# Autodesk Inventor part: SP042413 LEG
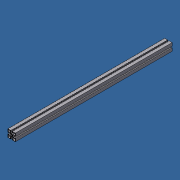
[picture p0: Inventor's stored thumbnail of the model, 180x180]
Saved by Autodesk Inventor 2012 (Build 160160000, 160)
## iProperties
Created: 2013-04
Part Number: SP042413 LEG
Material: Aluminum-6061
Description: PROFILE 45X45 UL
Document SubType Name: Modeling
Designer: Admin
Stock Number: 20.1063 PROFILE 45X45 UL
Density: 2.71 g/cm^3
FINISH: CLEAR ANODIZED
Author: Admin
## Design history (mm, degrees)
sketch "Sketch1"
  geometry: L1 (-4.1, -22.5)-(-4.1, -18) reference; L2 (-4.6, -18)-(-6.8, -18) reference; L3 (-6.8, -18)-(-6.8, -9.5) reference; L4 (-6.8, -9.5)-(-4.5, -7.2) reference; L5 (-4.5, -7.2)-(4.5, -7.2) reference; L6 (4.5, -7.2)-(6.8, -9.5) reference; L7 (6.8, -9.5)-(6.8, -18) reference; L8 (4.1, -18)-(4.1, -22.5) reference; L9 (22.5, -22.5)-(4.4, -22.5) reference; L10 (22.5, -4.4)-(22.5, -22.5) reference; L11 (22.5, -4.1)-(18, -4.1) reference; L12 (18, -4.6)-(18, -6.8) reference; L13 (18, -6.8)-(9.5, -6.8) reference; L14 (9.5, -6.8)-(7.2, -4.5) reference; L15 (7.2, -4.5)-(7.2, 4.5) reference; L16 (7.2, 4.5)-(9.5, 6.8) reference; L17 (9.5, 6.8)-(18, 6.8) reference; L18 (18, 4.1)-(22.5, 4.1) reference; L19 (4.4, 22.5)-(22.5, 22.5) reference; L20 (4.1, 22.5)-(4.1, 18) reference; L21 (4.6, 18)-(6.8, 18) reference; L22 (6.8, 18)-(6.8, 9.5) reference; L23 (6.8, 9.5)-(4.5, 7.2) reference; L24 (4.5, 7.2)-(-4.5, 7.2) reference; L25 (-4.5, 7.2)-(-6.8, 9.5) reference; L26 (-6.8, 9.5)-(-6.8, 18) reference; L27 (-4.1, 18)-(-4.1, 22.5) reference; L28 (-22.5, 4.1)-(-18, 4.1) reference; L29 (-18, 4.6)-(-18, 6.8) reference; L30 (-18, 6.8)-(-9.5, 6.8) reference; L31 (-9.5, 6.8)-(-7.2, 4.5) reference; L32 (-7.2, 4.5)-(-7.2, -4.5) reference; L33 (-7.2, -4.5)-(-9.5, -6.8) reference; L34 (-9.5, -6.8)-(-18, -6.8) reference; L35 (-18, -4.1)-(-22.5, -4.1) reference; L36 (-22.5, -22.5)-(-22.5, -4.4) reference; L37 (-21.1, -6.5)-(-19.4, -6.5) reference; L38 (-19.4, -6.5)-(-19.4, -8.2) reference; L39 (-8.2, -19.4)-(-6.5, -19.4) reference; L40 (-6.5, -19.4)-(-6.5, -21.1) reference; L41 (6.5, -21.1)-(6.5, -19.4) reference; L42 (6.5, -19.4)-(8.2, -19.4) reference; L43 (19.4, -8.2)-(19.4, -6.5) reference; L44 (19.4, -6.5)-(21.1, -6.5) reference; L45 (21.1, 6.5)-(19.4, 6.5) reference; L46 (19.4, 6.5)-(19.4, 8.2) reference; L47 (8.2, 19.4)-(6.5, 19.4) reference; L48 (6.5, 19.4)-(6.5, 21.1) reference; L49 (-6.5, 21.1)-(-6.5, 19.4) reference; L50 (-6.5, 19.4)-(-8.2, 19.4) reference; L51 (-19.4, 8.2)-(-19.4, 6.5) reference; L52 (-19.4, 6.5)-(-21.1, 6.5) reference; L53 (-3.537, -5.8)-(-1.188, -3.451) reference; L54 (-3.451, -1.188)-(-5.8, -3.537) reference; L55 (-5.8, -3.537)-(-5.8, 3.537) reference; L56 (-5.8, 3.537)-(-3.451, 1.188) reference; L57 (-1.188, 3.451)-(-3.537, 5.8) reference; L58 (-3.537, 5.8)-(3.537, 5.8) reference; L59 (3.537, 5.8)-(1.188, 3.451) reference; L60 (3.451, 1.188)-(5.8, 3.537) reference; L61 (5.8, 3.537)-(5.8, -3.537) reference; L62 (5.8, -3.537)-(3.451, -1.188) reference; L63 (1.188, -3.451)-(3.537, -5.8) reference; L64 (3.537, -5.8)-(-3.537, -5.8) reference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; A1 r 3.65 centre (0, 0) between (3.287, 1.588) and (1.588, 3.287) reference; A2 r 3.65 centre (0, 0) between (1.588, 3.287) and (1.188, 3.451) reference; A3 r 3.65 centre (0, 0) between (-1.188, 3.451) and (-3.451, 1.188) reference; A4 r 3.65 centre (0, 0) between (-3.451, -1.188) and (-3.287, -1.588) reference; A5 r 3.65 centre (0, 0) between (-3.287, -1.588) and (-1.188, -3.451) reference; A6 r 3.65 centre (0, 0) between (1.188, -3.451) and (1.588, -3.287) reference; A7 r 3.65 centre (0, 0) between (1.588, -3.287) and (3.451, -1.188) reference; A8 r 3.65 centre (0, 0) between (3.451, 1.188) and (3.287, 1.588) reference
  constraints: 192 end point, 32 horizontal, 30 vertical, 16 point on circle, 8 centre point, 8 parallel, 5 perpendicular, 134 other
extrude "Extrusion1" new body sketch "Sketch1" distance "d0" = 938.276 (= -TABLE_TOP_THICKNESS + Height - LEVELER_HEIGHT); taper "d1" = 0 deg
body "Solid1"
other parameters: "Height" = 1066.8 [user parameter; used in 1 equation term], "Width" = 1828.8 [user parameter], "DEPTH" = 914.4 [user parameter], "LOWER_INSET" = 203.2 [user parameter], "TABLE_TOP_THICKNESS" = 12.7 [user parameter; used in 1 equation term], "LEVELER_HEIGHT" = 115.824 [user parameter; used in 1 equation term], "TOP_OVERHANG" = 25.4 [user parameter]
